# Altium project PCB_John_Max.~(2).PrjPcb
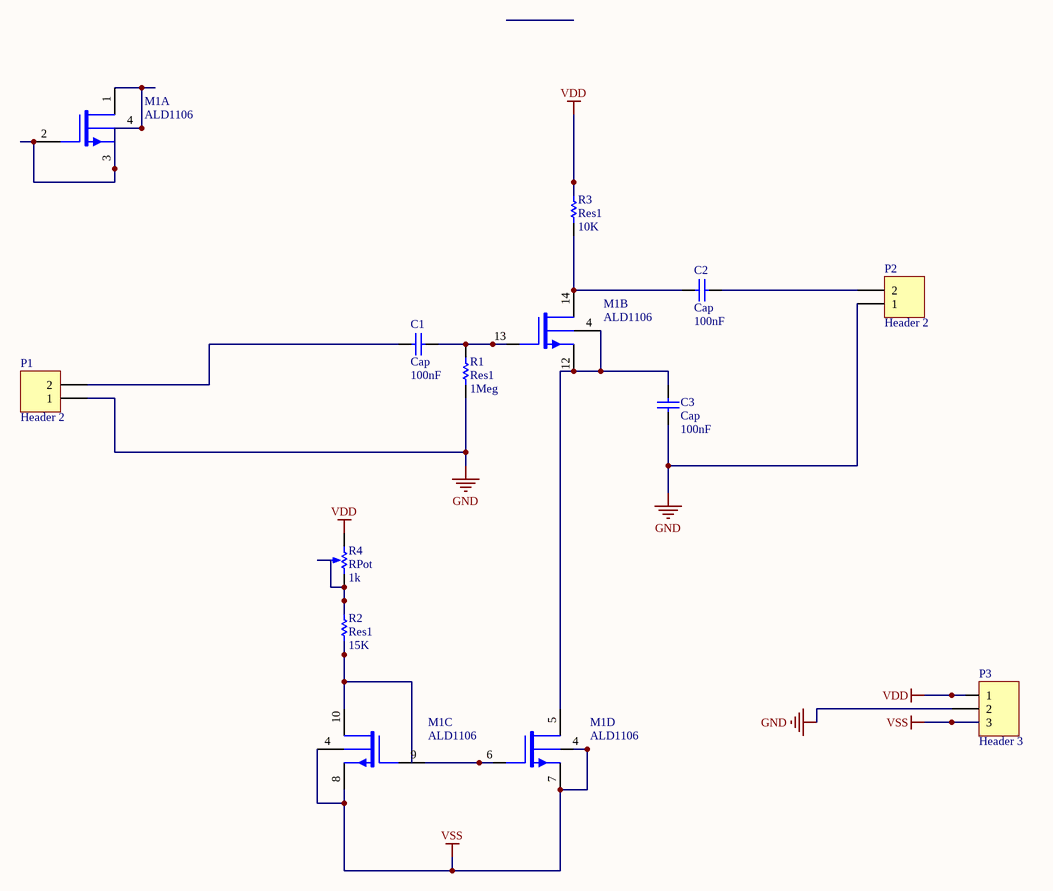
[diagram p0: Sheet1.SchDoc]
1 sheet, 11 parts. Net scope: global (net labels, ports and power ports of the same name join across sheets).
Board file: PCB1.PcbDoc

## Sheet Sheet1.SchDoc
size A4

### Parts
C1  Cap  value 100nF  [RAD-0.3]
C2  Cap  value 100nF  [RAD-0.3]
C3  Cap  value 100nF  [RAD-0.3]
M1  ALD1106  [DIP-14]  (parts A,B,C,D of 4)
P1  Header 2  [HDR1X2]
P2  Header 2  [HDR1X2]
P3  Header 3  [HDR1X3]
R1  Res1  value 1Meg  [AXIAL-0.3]
R2  Res1  value 15K  [AXIAL-0.3]
R3  Res1  value 10K  [AXIAL-0.3]
R4  RPot  value 1k  [VR5]

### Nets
GND: C3.2 P1.1 P2.1 P3.2 R1.1
VDD: P3.1 R3.2 R4.1(TOP)
VSS: M1.4(V-) M1.7(SN4) M1.8(SN3) P3.3
NetC1_1: C1.1 P1.2
NetC1_2: C1.2 M1.13(GN2) R1.2
NetC2_1: C2.1 M1.14(DN2) R3.1
NetC2_2: C2.2 P2.2
NetC3_1: C3.1 M1.4(V-) M1.5(DN4) M1.12(SN2)
NetM1_1: M1.1(DN1) M1.2(GN1) M1.3(SN1) M1.4(V-)
NetM1_6: M1.6(GN4) M1.9(GN3)
NetM1_10: M1.10(DN3) R2.1
NetR2_2: R2.2 R4.2(TAP) R4.3(BOT)

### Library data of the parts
C1-C3 = Cap: Capacitor
M1 = ALD1106: Quad N-channel matched MOSFET array
P1 P2 = Header 2: Header, 2-Pin
P3 = Header 3: Header, 3-Pin
R1-R3 = Res1: Resistor
R4 = RPot: Potentiometer; Sim Note: Enter the Resistance value and the set point into parameter fields.; Set Position: 0.5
